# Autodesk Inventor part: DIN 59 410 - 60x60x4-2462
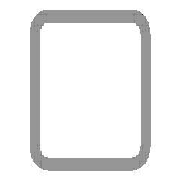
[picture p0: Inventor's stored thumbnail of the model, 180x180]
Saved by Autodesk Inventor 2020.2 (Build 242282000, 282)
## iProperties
Manager: www.cadconsulting.pl
Company: Fabian Stasiak CAD Consulting
IsCustomPart: 1
_CCFamilyMember: 60
_CCFamilyDisplayName: DIN 59410 (Kwadrat) - Rurki stalowe o przekroju kwadratowym formowane na gorąco
_FrameMemberDoc: Frame Member File
_Version: 15.0.0
_GetPNFromCC: 1
Created: 2015-01
Part Number: DIN 59 410 - 60x60x4-2462
Material: Stal, miękka
Description: Rurki stalowe o przekroju kwadratowym formowane na gorąco
Document SubType Name: Modellieren
Standard: DIN
Designer: F.Stasiak
Standards Organization: DIN
Language: pl-PL
Size Designation: 60x60x4
Categories: <MemberInstance><Categories><Category DisplayName="Kształtowniki konstrukcyjne" InternalName="089c4875-fa83-4c05-b084-43b9cc11f5ed" Mnemonic="GRDR"><CategoryPar
Stock Number: 60x60x4
Density: 7.85 g/cm^3
Appearance: Częściowo polerowana
Catalog Web Link: www.expertbooks.pl
G_L: 2462,000 mm
G_W: 60,000 mm
G_H: 60,000 mm
+375225A0-A35A-40A9-B2A5-BDF55DF89B01+CUTDETAIL1: Wytnij
Author: F.Stasiak
Subject: Zbiór ćwiczeń. Autodesk Inventor 2020. Kurs Professional
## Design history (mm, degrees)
node "Płaszczyzna początkowa"
node "Płaszczyzna końcowa"
sketch "Szkic1"
  geometry: L1 (-22, 30)-(22, 30); L2 (30, 22)-(30, -22); L3 (22, -30)-(-22, -30); L4 (-30, -22)-(-30, 22); L5 (-44.32, 0)-(44.32, 0) reference; L6 (0, -44.32)-(0, 44.32) reference; L7 (-22, 26)-(22, 26); L8 (26, 22)-(26, -22); L9 (22, -26)-(-22, -26); L10 (-26, -22)-(-26, 22); A1 r 8 centre (-22, 22) between (-22, 30) and (-30, 22); A2 r 8 centre (22, 22) between (30, 22) and (22, 30); A3 r 8 centre (22, -22) between (22, -30) and (30, -22); A4 r 8 centre (-22, -22) between (-30, -22) and (-22, -30); A5 r 4 centre (-22, 22) between (-22, 26) and (-26, 22); A6 r 4 centre (22, 22) between (26, 22) and (22, 26); A7 r 4 centre (22, -22) between (22, -26) and (26, -22); A8 r 4 centre (-22, -22) between (-26, -22) and (-22, -26); 3 further points
  constraints: 16 end point, 16 point on circle, 8 centre point, 8 tangent, 6 point on line, 4 parallel, 3 equal radius, 3 perpendicular, 1 horizontal, 7 other
  dimensions: "b" = 60 distance of point (-30, 30) point (30, 30); "msp_r" = 8 radius of A1 (= 2 x ParT); "d8" = 30 distance between parallel lines of L4 L6 (= d9); "d9" = 30 distance between parallel lines of L3 L5 (= 0.5 x b); "d10" = 4 distance between parallel lines of L3 L9 (= ParT)
extrude "Bryła" new body sketch "Szkic1" taper "d4" = 0 deg; stored distance "NLG" = 10
node "Driven Length"
  sketch "Sketch2"
    geometry: L1 (0, 0)-(10, 0) reference
    constraints: 2 end point, 1 horizontal
  workplane "Work Plane3"
  sketch "Sketch3"
    geometry: L1 (-2, 38)-(12, 38) reference; L2 (-2, 2500)-(12, 2500) reference
    dimensions: "d14" = 2462 distance between parallel lines of L1 L2 (derived)
node "Płaszczyzna konstrukcyjna4"
feature "Podział1"
body "Solid1"
other parameters: "ParT" = 4, "G_OFFSET_START" = -38 [user parameter; used in 1 equation term], "G_OFFSET_END" = 0 [user parameter; used in 1 equation term], "d11" = 38 (= -G_OFFSET_START), "G_L" = 2462 (= d14) [user parameter], "d13" = 90 deg
